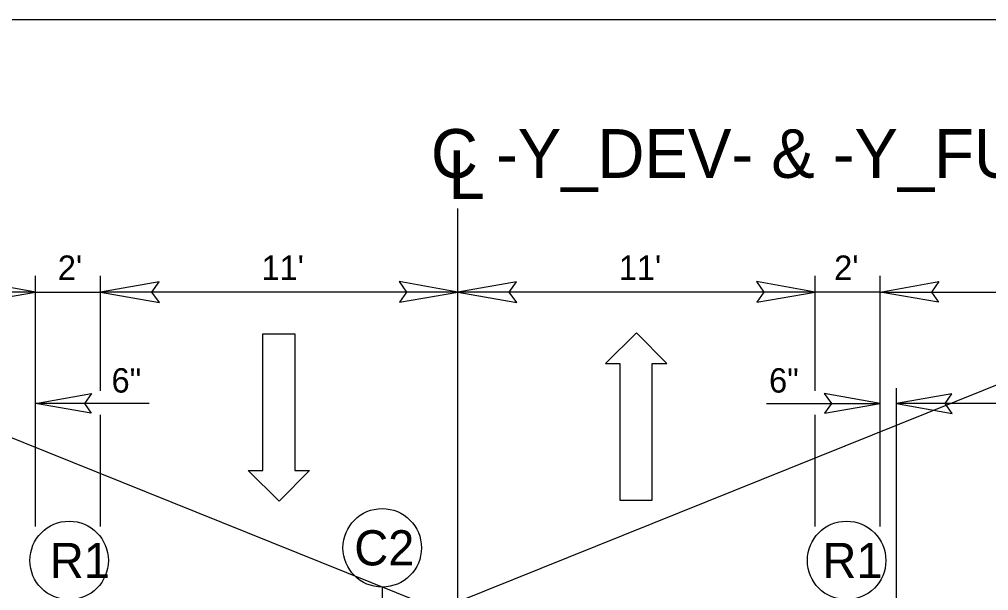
# Model space of a CAD drawing. Extents: x 1487909 to 1489267, y 497866 to 499814.
# Drawn here: x 1489209.2 to 1489239.04, y 498163 to 498180.57 of the extents above; entities that cross this region are included whole.
import ezdxf

# ---------------------------------------------------------------- set-up
doc = ezdxf.new("R2010")
doc.units = 0
for name, color, linetype in [('Prop Dimension', 7, 'Continuous'), ('Prop Dimension Text', 7, 'Continuous'), ('Prop Lane Arrow CELL', 7, 'Continuous'), ('Prop Terminator CELL', 7, 'Continuous'), ('Scratch_Level_3', 7, 'Continuous'), ('Typical Hinge Slope Interstate CELL', 7, 'Continuous'), ('Typical ID Circle CELL', 7, 'Continuous'), ('Typical Text ID Circle CELL', 7, 'Continuous')]:
    doc.layers.add(name, color=color, linetype=linetype)

msp = doc.modelspace()

# ---------------------------------------------------------------- linework, layer by layer
at = {"layer": 'Prop Dimension'}
for p, q in [((1489222.699, 498156.69), (1489222.699, 498174.752)), ((1489209.699, 498164.975), (1489209.699, 498172.686)), ((1489211.699, 498169.144), (1489211.699, 498172.686)), ((1489233.699, 498169.144), (1489233.699, 498172.686)), ((1489235.699, 498164.975), (1489235.699, 498172.686)), ((1489209.699, 498172.186), (1489195.199, 498172.186)), ((1489209.699, 498172.186), (1489211.699, 498172.186)), ((1489222.699, 498172.186), (1489211.699, 498172.186)), ((1489233.699, 498172.186), (1489222.699, 498172.186)), ((1489235.699, 498172.186), (1489233.699, 498172.186)), ((1489235.699, 498172.186), (1489250.199, 498172.186)), ((1489236.199, 498160.621), (1489236.199, 498169.227)), ((1489213.193, 498168.756), (1489209.699, 498168.756)), ((1489232.204, 498168.756), (1489235.699, 498168.756)), ((1489244.199, 498168.756), (1489236.199, 498168.756)), ((1489211.699, 498164.975), (1489211.699, 498168.407)), ((1489233.699, 498164.975), (1489233.699, 498168.407))]:
    msp.add_line(p, q, dxfattribs=at)
at = {"layer": 'Prop Lane Arrow CELL'}
for p, q in [((1489216.689, 498166.698), (1489216.689, 498170.898)), ((1489216.689, 498170.898), (1489217.679, 498170.898)), ((1489217.679, 498170.898), (1489217.679, 498166.698)), ((1489228.199, 498170.932), (1489227.239, 498169.987)), ((1489229.129, 498169.987), (1489228.199, 498170.932)), ((1489227.239, 498169.987), (1489227.689, 498169.987)), ((1489227.689, 498169.987), (1489227.689, 498165.787)), ((1489228.679, 498165.787), (1489228.679, 498169.987)), ((1489228.679, 498169.987), (1489229.129, 498169.987)), ((1489217.199, 498165.753), (1489216.239, 498166.698)), ((1489216.239, 498166.698), (1489216.689, 498166.698)), ((1489218.129, 498166.698), (1489217.199, 498165.753)), ((1489217.679, 498166.698), (1489218.129, 498166.698)), ((1489227.689, 498165.787), (1489228.679, 498165.787))]:
    msp.add_line(p, q, dxfattribs=at)
at = {"layer": 'Prop Terminator CELL'}
for points in [[(1489207.899, 498171.876), (1489209.699, 498172.186), (1489207.889, 498172.506), (1489208.119, 498172.186)], [(1489213.499, 498172.496), (1489211.699, 498172.186), (1489213.509, 498171.866), (1489213.279, 498172.186)], [(1489220.899, 498171.876), (1489222.699, 498172.186), (1489220.889, 498172.506), (1489221.119, 498172.186)], [(1489224.499, 498172.496), (1489222.699, 498172.186), (1489224.509, 498171.866), (1489224.279, 498172.186)], [(1489231.899, 498171.876), (1489233.699, 498172.186), (1489231.889, 498172.506), (1489232.119, 498172.186)], [(1489237.499, 498171.876), (1489235.699, 498172.186), (1489237.509, 498172.506), (1489237.279, 498172.186)], [(1489211.409, 498168.461), (1489209.699, 498168.756), (1489211.418, 498169.06), (1489211.2, 498168.756)], [(1489233.989, 498168.461), (1489235.699, 498168.756), (1489233.979, 498169.06), (1489234.198, 498168.756)], [(1489237.909, 498169.05), (1489236.199, 498168.756), (1489237.918, 498168.452), (1489237.7, 498168.756)]]:
    msp.add_lwpolyline(points, close=True, dxfattribs=at)
at = {"layer": 'Scratch_Level_3'}
for p, q in [((1489176.952, 498144.269), (1489267.234, 498180.571)), ((1489267.234, 498144.269), (1489176.952, 498180.571))]:
    msp.add_line(p, q, dxfattribs=at)
msp.add_lwpolyline([(1489176.952, 498180.571), (1489267.234, 498180.571), (1489267.234, 498144.269), (1489176.952, 498144.269)], close=True, dxfattribs=at)
at = {"layer": 'Typical ID Circle CELL'}
msp.add_line((1489220.369, 498163.108), (1489220.369, 498159.985), dxfattribs=at)
for centre in [(1489220.369, 498164.317), (1489210.731, 498163.929), (1489234.666, 498163.929)]:
    msp.add_circle(centre, 1.208, dxfattribs=at)

# ---------------------------------------------------------------- texts
at = {"layer": 'Prop Dimension Text'}
for s, p in [("2'", (1489210.382, 498172.559)), ("11'", (1489216.651, 498172.559)), ("11'", (1489227.651, 498172.559)), ("2'", (1489234.283, 498172.559)), ('6"', (1489212.036, 498169.092)), ('6"', (1489232.279, 498169.092))]:
    msp.add_text(s, height=0.75, dxfattribs=at).set_placement(p)
at = {"layer": 'Typical Hinge Slope Interstate CELL'}
for s, p in [('C -Y_DEV- & -Y_FUT-', (1489221.868, 498175.697)), ('L', (1489222.408, 498175.048))]:
    msp.add_text(s, height=1.5, dxfattribs=at).set_placement(p)
at = {"layer": 'Typical Text ID Circle CELL'}
for s, p in [('C2', (1489219.509, 498163.776)), ('R1', (1489210.137, 498163.388)), ('R1', (1489233.923, 498163.388))]:
    msp.add_text(s, height=1.0817, dxfattribs=at).set_placement(p)

doc.saveas('drawing.dxf')
